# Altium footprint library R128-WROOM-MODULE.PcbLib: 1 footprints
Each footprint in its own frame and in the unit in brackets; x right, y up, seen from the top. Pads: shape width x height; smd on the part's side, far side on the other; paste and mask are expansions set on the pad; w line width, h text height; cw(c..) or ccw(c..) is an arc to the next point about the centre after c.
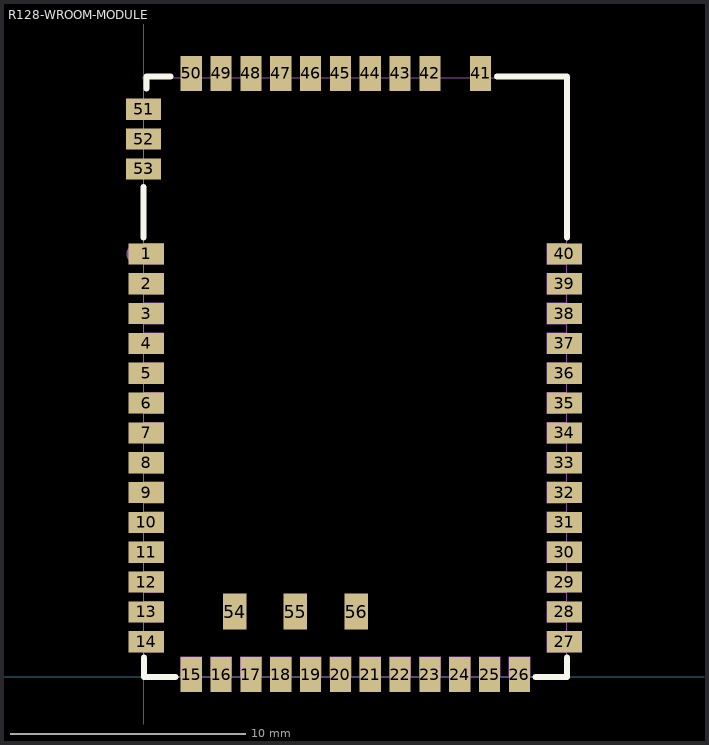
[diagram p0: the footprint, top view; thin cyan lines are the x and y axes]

## R128-WROOM-MODULE [mm]
pads (56):
  rect 1.5x0.9 smd paste+0 mask+0.05: 1(0.1,18.009) 2(0.1,16.739) 3(0.1,15.469) 4(0.1,14.199) 5(0.1,12.929) 6(0.1,11.659) 7(0.1,10.389) 8(0.1,9.119) 9(0.1,7.849) 10(0.1,6.579) 11(0.1,5.309) 12(0.1,4.039) 13(0.1,2.769) 14(0.1,1.499) 27(17.9,1.499) 28(17.9,2.769) 29(17.9,4.039) 30(17.9,5.309) 31(17.9,6.579) 32(17.9,7.849) 33(17.9,9.119) 34(17.9,10.389) 35(17.9,11.659) 36(17.9,12.929) 37(17.9,14.199) 38(17.9,15.469) 39(17.9,16.739) 40(17.9,18.009) 51(-0.017,24.168) 52(-0.017,22.898) 53(-0.017,21.628)
  rect 0.9x1.5 smd paste+0 mask+0.05: 15(2.015,0.1) 16(3.285,0.1) 17(4.555,0.1) 18(5.825,0.1) 19(7.095,0.1) 20(8.365,0.1) 21(9.635,0.1) 22(10.905,0.1) 23(12.175,0.1) 24(13.445,0.1) 25(14.715,0.1) 26(15.985,0.1) 41(14.334,25.692) 42(12.175,25.692) 43(10.905,25.692) 44(9.635,25.692) 45(8.365,25.692) 46(7.095,25.692) 47(5.825,25.692) 48(4.555,25.692) 49(3.285,25.692) 50(2.015,25.692)
  rect 1x1.524 smd mask+0.051: 54(3.859,2.781) 55(6.45,2.781) 56(9.041,2.781)
Top Overlay:
  lines w0.254: -0.017,18.707 -0.017,20.866 ; 0,0.818 0,0 1.334,0 ; 0.11,25.057 0.11,25.565 1.126,25.565 ; 15.032,25.565 18.017,25.565 18.017,18.707 ; 16.666,0 18,0 18,0.818
Mechanical 6:
  circle w0.4: c-0.35,18 r0.2
Mechanical 15:
  drawing of 45 lines, arcs and shapes, not listed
